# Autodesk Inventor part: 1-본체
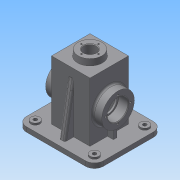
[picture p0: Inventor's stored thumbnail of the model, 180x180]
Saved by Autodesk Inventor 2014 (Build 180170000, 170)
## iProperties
Created: 2015-12
Part Number: 1-본체
Material: Generic
Document SubType Name: Modeling
Designer: Administrator
Density: 1 g/cm^3
Appearance: Default
Author: Administrator
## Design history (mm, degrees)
sketch "스케치1"
  geometry: L1 (-50, -52.5)-(50, -52.5); L2 (60, -42.5)-(60, 42.5); L3 (50, 52.5)-(-50, 52.5); L4 (-60, 42.5)-(-60, -42.5); L5 (-60, -52.5)-(60, 52.5); L6 (60, -52.5)-(-60, 52.5); A1 r 10 centre (-50, 42.5) between (-50, 52.5) and (-60, 42.5); A2 r 10 centre (50, 42.5) between (60, 42.5) and (50, 52.5); A3 r 10 centre (-50, -42.5) between (-60, -42.5) and (-50, -52.5); A4 r 10 centre (50, -42.5) between (50, -52.5) and (60, -42.5); 1 further point
  constraints: 12 end point, 8 point on circle, 8 point on line, 8 tangent, 4 centre point, 3 equal radius, 2 midpoint, 2 parallel, 1 horizontal, 1 perpendicular
  dimensions: "d0" = 120 distance of L5.end L6.end; "d1" = 105 distance of L6.start L5.end; "d2" = 10 radius of A1
extrude "돌출1" new body sketch "스케치1" distance "d3" = 2; taper "d4" = 0 deg
sketch "스케치2"
  geometry: L1 (50, 52.5)-(-50, 52.5) reference; L2 (-60, 42.5)-(-60, -42.5) reference; L3 (-50, -52.5)-(50, -52.5) reference; L4 (60, -42.5)-(60, 42.5) reference; L5 (-50, 57.5)-(50, 57.5); L6 (65, 42.5)-(65, -42.5); L7 (50, -57.5)-(-50, -57.5); L8 (-65, -42.5)-(-65, 42.5); A1 r 10 centre (-50, 42.5) between (-50, 52.5) and (-60, 42.5) reference; A2 r 10 centre (-50, -42.5) between (-60, -42.5) and (-50, -52.5) reference; A3 r 10 centre (50, -42.5) between (50, -52.5) and (60, -42.5) reference; A4 r 10 centre (50, 42.5) between (60, 42.5) and (50, 52.5) reference; A5 r 15 centre (50, 42.5) between (65, 42.5) and (50, 57.5); A6 r 15 centre (50, -42.5) between (50, -57.5) and (65, -42.5); A7 r 15 centre (-50, -42.5) between (-65, -42.5) and (-50, -57.5); A8 r 15 centre (-50, 42.5) between (-50, 57.5) and (-65, 42.5); 1 further point
  constraints: 8 end point, 8 point on circle, 4 centre point, 7 other
  dimensions: "d5" = 5 distance between parallel lines of L1 L5
extrude "돌출2" join sketch "스케치2" distance "d6" = 8; taper "d7" = 0 deg
sketch "스케치3"
  geometry: L1 (-32.5, -32.5)-(32.5, -32.5); L2 (32.5, -32.5)-(32.5, 32.5); L3 (32.5, 32.5)-(-32.5, 32.5); L4 (-32.5, 32.5)-(-32.5, -32.5); L5 (-32.5, -32.5)-(32.5, 32.5); L6 (32.5, -32.5)-(-32.5, 32.5); 1 further point
  constraints: 12 end point, 2 midpoint, 2 parallel, 2 perpendicular, 1 horizontal
  dimensions: "d8" = 65 distance of L2.end L3.end
extrude "돌출3" join sketch "스케치3" distance "d9" = 100; taper "d10" = 0 deg
feature "쉘1" dims "d11" = 10, "d12" = 5
sketch "스케치5"
  geometry: L1 (10, 75)-(10, -10) reference; C1 r 27.5 at (-45, 32.5); 2 further points
  constraints: 1 centre point, 1 horizontal alignment, 1 midpoint
  dimensions: "d15" = 55 diameter of C1; "d16" = 55 distance from line of C1.centre L1
extrude "돌출4" join sketch "스케치5" distance "d17" = 15; taper "d18" = 0 deg
sketch "스케치6"
  geometry: C1 r 27.5 at (0, 0) reference; 2 further points
  constraints: 1 vertical alignment
  dimensions: "d19" = 21 distance of C1.centre point (0, 21)
hole "구멍1" sketch "스케치6" at (0, 21) diameter "d20" = 3.242; stored, may be unused: countersink angle "d24" = 90 deg, drill point angle "d26" = 118 deg; dims "d21" = 8, "d22" = 4, "d23" = 2, "d25" = 10
hole "구멍2" diameter "d32" = 30; stored, may be unused: countersink angle "d36" = 90 deg, drill point angle "d38" = 0 deg; dims "d30" = 10, "d31" = 10, "d33" = 8, "d34" = 35, "d35" = 17, "d37" = 35
node "작업 평면1"
sketch "스케치7"
  geometry: C1 r 20 at (0, 0); 1 further point
  constraints: 1 centre point, 1 coincident
  dimensions: "d40" = 40 diameter of C1
extrude "돌출5" join sketch "스케치7" stored distance "d41" = 15; taper "d42" = 5 deg
sketch "스케치8"
  geometry: C1 r 20 at (0, 0) reference; 1 further point
  constraints: 1 vertical alignment
  dimensions: "d43" = 14.5 distance of C1.centre point (0, 14.5)
hole "구멍3" sketch "스케치8" at (0, 14.5) diameter "d44" = 2.459; stored, may be unused: countersink angle "d48" = 90 deg, drill point angle "d50" = 118 deg; dims "d45" = 7, "d46" = 35, "d47" = 17, "d49" = 9
hole "구멍4" diameter "d56" = 21; stored, may be unused: countersink angle "d60" = 90 deg, drill point angle "d62" = 0 deg; dims "d54" = 10, "d55" = 10, "d57" = 7, "d58" = 35, "d59" = 17, "d61" = 9
sketch "스케치9"
  geometry: L1 (32.5, 10)-(32.5, 110) reference; L2 (42.5, 10)-(-42.5, 10) reference; L3 (57.5, 10)-(42.5, 10) reference; L4 (47.5, 10)-(32.5, 95.069); L5 (57.5, 2)-(57.5, 10) reference; 1 further point
  constraints: 2 end point, 2 point on line
  dimensions: "d63" = 10 distance of L3.start L4.start; "d64" = 10 deg angle of L5 L4
extrude "돌출6" join sketch "스케치9" stored distance "d65" = 10; taper "d66" = 0 deg
sketch "스케치10"
  geometry: L1 (32.5, 10)-(32.5, 110) reference; L2 (50, 10)-(-50, 10) reference; L3 (47.5, 27.5)-(32.5, 27.5) reference; L4 (27.5, 0)-(27.5, 105) reference; L5 (42.5, 10)-(42.5, 31); L6 (42.5, 31)-(31, 31); L7 (31, 31)-(31, 7); L8 (31, 7)-(42.5, 8); L9 (42.5, 8)-(42.5, 10); 2 further points
  constraints: 10 end point, 2 parallel, 2 perpendicular, 2 point on line
  dimensions: "d130" = 15 distance between parallel lines of L5 L4; "d131" = 4.96974 deg angle of L2 L8; "d132" = 21 distance between parallel lines of L2 L6; "d133" = 1.5 distance between parallel lines of L1 L7; "d134" = 1.34276 distance from line of L2.start L8; "d135" = 10 distance from line of point (42.5, 27.5) L1
extrude "돌출7" join sketch "스케치10" stored distance "d68" = 6; taper "d69" = 0 deg
sketch "스케치11"
  geometry: C1 r 7.5 at (-50, 42.5); C2 r 7.5 at (50, 42.5); C3 r 7.5 at (50, -42.5); C4 r 7.5 at (-50, -42.5); A1 r 15 centre (-50, 42.5) between (-50, 57.5) and (-65, 42.5) reference; A2 r 15 centre (-50, -42.5) between (-65, -42.5) and (-50, -57.5) reference; A3 r 15 centre (50, -42.5) between (50, -57.5) and (65, -42.5) reference; A4 r 15 centre (50, 42.5) between (65, 42.5) and (50, 57.5) reference; 1 further point
  constraints: 4 centre point, 4 coincident
  dimensions: "d70" = 15 diameter of C1; "d71" = 15 diameter of C2; "d72" = 15 diameter of C3; "d73" = 15 diameter of C4
extrude "돌출8" join sketch "스케치11" distance "d74" = 3; taper "d75" = 0 deg
hole "구멍5" diameter "d78" = 6; stored, may be unused: countersink angle "d82" = 90 deg, drill point angle "d84" = 0 deg; dims "d76" = 10, "d77" = 10, "d79" = 7, "d80" = 35, "d81" = 17, "d83" = 9
hole "구멍6" diameter "d87" = 6; stored, may be unused: countersink angle "d91" = 90 deg, drill point angle "d93" = 0 deg; dims "d85" = 10, "d86" = 10, "d88" = 7, "d89" = 35, "d90" = 17, "d92" = 9
hole "구멍7" diameter "d96" = 6; stored, may be unused: countersink angle "d100" = 90 deg, drill point angle "d102" = 0 deg; dims "d94" = 10, "d95" = 10, "d97" = 7, "d98" = 35, "d99" = 17, "d101" = 9
hole "구멍8" diameter "d105" = 6; stored, may be unused: countersink angle "d109" = 90 deg, drill point angle "d111" = 0 deg; dims "d103" = 10, "d104" = 10, "d106" = 7, "d107" = 35, "d108" = 17, "d110" = 9
node "작업 평면2"
sketch "스케치15"
  geometry: L1 (10, 52.5)-(10, 12.5) reference; L2 (-100, 65)-(0, 65) reference; 2 further points
  constraints: 1 other
  dimensions: "d119" = 26 distance from line of L1 point (-16, 32.5); "d120" = 32.5 distance from line of point (-16, 32.5) L2
extrude "돌출9" join sketch "스케치15" stored distance "d121" = 3; taper "d122" = 0 deg
chamfer "모따기1" distance "d123" = 1; stored, may be unused: second distance "d124" = 2, angle "d125" = 45 deg
fillet "모깎기1" dims "d126" = 0.3
fillet "모깎기4" dims "d129" = 3
fillet "모깎기5" dims "d136" = 3
node "솔리드1"
pattern_circular "원형 패턴1" dims angle "d28" = 360 deg
mirror "대칭1"
pattern_circular "원형 패턴2" dims angle "d52" = 360 deg
mirror "대칭2"
mirror "대칭3"
other parameters: "d118" = 0.5
